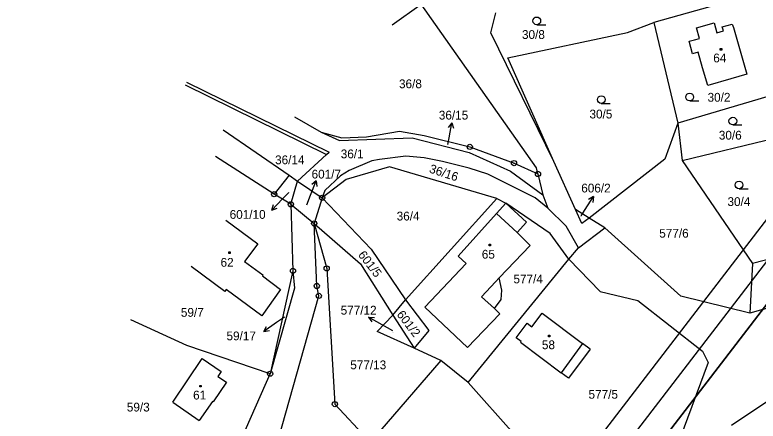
# Model space of a CAD drawing. Extents: x -866656 to -858817, y -1041816 to -1038653.
# Drawn here: x -862913.4 to -862769.6, y -1039656.9 to -1039578.3 of the extents above; entities that cross this region are included whole.
import ezdxf

# ---------------------------------------------------------------- set-up
doc = ezdxf.new("R2010")
doc.units = 0
for name, color, linetype in [('tisk ramy', 7, 'Continuous'), ('Vrstva 1', 7, 'Continuous'), ('Vrstva 2', 7, 'Continuous')]:
    doc.layers.add(name, color=color, linetype=linetype)

msp = doc.modelspace()

# ---------------------------------------------------------------- linework, layer by layer
at = {"layer": 'tisk ramy'}
for points in [[(-862750.99, -1040083.46), (-861983.98, -1039083.83), (-862219.6, -1038903.04), (-862986.61, -1039902.67)], [(-862979.6, -1039901.75), (-862218.68, -1038910.05), (-861990.99, -1039084.75), (-862751.92, -1040076.45)], [(-862752.84, -1040069.45), (-862122.79, -1039248.31), (-862342.55, -1039079.69), (-862972.6, -1039900.83)], [(-862972.6, -1039900.83), (-862342.55, -1039079.69), (-862122.79, -1039248.31), (-862752.84, -1040069.45)]]:
    msp.add_lwpolyline(points, close=True, dxfattribs=at)
at = {"layer": 'Vrstva 1'}
for p, q in [((-862770.51, -1039574.3), (-862789.82, -1039579.76)), ((-862840.39, -1039580.21), (-862834.77, -1039576.2)), ((-862812.5, -1039607.85), (-862834.77, -1039576.2)), ((-862821.31, -1039581.76), (-862820.36, -1039577.84)), ((-862812.44, -1039580.18), (-862810.69, -1039580.18)), ((-862794.91, -1039581.68), (-862789.82, -1039579.76)), ((-862789.82, -1039579.76), (-862785.16, -1039599.23)), ((-862781.58, -1039580.79), (-862778.16, -1039579.81)), ((-862780.99, -1039582.81), (-862781.58, -1039580.79)), ((-862778.16, -1039579.81), (-862777.61, -1039581.73)), ((-862776.57, -1039580.59), (-862774.65, -1039580.03)), ((-862776.35, -1039581.36), (-862776.57, -1039580.59)), ((-862774.65, -1039580.03), (-862774.43, -1039580.71)), ((-862774.43, -1039580.71), (-862771.84, -1039589.74)), ((-862809.11, -1039606.61), (-862821.31, -1039581.76)), ((-862818.05, -1039586.59), (-862794.91, -1039581.68)), ((-862777.61, -1039581.73), (-862776.35, -1039581.36)), ((-862782.99, -1039583.38), (-862781.94, -1039583.07)), ((-862782.3, -1039585.8), (-862782.99, -1039583.38)), ((-862781.94, -1039583.07), (-862780.99, -1039582.81)), ((-862776.97, -1039584.76), (-862776.67, -1039584.76)), ((-862776.97, -1039585.06), (-862776.97, -1039584.76)), ((-862776.67, -1039585.06), (-862776.97, -1039585.06)), ((-862776.67, -1039584.76), (-862776.67, -1039585.06)), ((-862781.25, -1039585.5), (-862782.3, -1039585.8)), ((-862780.38, -1039588.48), (-862781.25, -1039585.5)), ((-862809.11, -1039606.61), (-862818.05, -1039586.59)), ((-862779.39, -1039591.95), (-862780.38, -1039588.48)), ((-862774.91, -1039590.63), (-862779.39, -1039591.95)), ((-862771.84, -1039589.74), (-862774.91, -1039590.63)), ((-862880.42, -1039591.79), (-862853.1, -1039605.3)), ((-862880.14, -1039591.3), (-862852.58, -1039604.82)), ((-862765.99, -1039593.51), (-862785.16, -1039599.23)), ((-862782.87, -1039594.91), (-862781.12, -1039594.91)), ((-862799.97, -1039595.4), (-862798.22, -1039595.4)), ((-862859.31, -1039597.97), (-862854.15, -1039600.97)), ((-862828.88, -1039599.13), (-862829.54, -1039600.02)), ((-862829.4, -1039602.08), (-862828.88, -1039599.13)), ((-862828.88, -1039599.13), (-862828.56, -1039600.2)), ((-862785.16, -1039599.23), (-862787.66, -1039606.21)), ((-862785.16, -1039599.23), (-862784.34, -1039606.44)), ((-862873.05, -1039600.53), (-862860.32, -1039609.3)), ((-862845.36, -1039601.88), (-862838.98, -1039600.73)), ((-862838.98, -1039600.73), (-862834.19, -1039601.57)), ((-862784.34, -1039606.44), (-862761.09, -1039600.84)), ((-862774.53, -1039599.56), (-862772.78, -1039599.56)), ((-862854.15, -1039600.97), (-862850.56, -1039602.54)), ((-862854.15, -1039600.97), (-862850.16, -1039602.05)), ((-862850.56, -1039602.54), (-862836.56, -1039602.05)), ((-862850.16, -1039602.05), (-862845.36, -1039601.88)), ((-862836.56, -1039602.05), (-862825.52, -1039604.89)), ((-862834.19, -1039601.57), (-862825.39, -1039603.8)), ((-862829.63, -1039603.35), (-862829.4, -1039602.08)), ((-862825.39, -1039603.8), (-862816.84, -1039606.94)), ((-862853.1, -1039605.3), (-862852.58, -1039604.82)), ((-862825.52, -1039604.89), (-862817.53, -1039608.5)), ((-862863.21, -1039612.96), (-862874.56, -1039605.69)), ((-862853.1, -1039605.3), (-862858.68, -1039610.42)), ((-862844.36, -1039606.52), (-862848.69, -1039608.37)), ((-862842.85, -1039606.22), (-862844.36, -1039606.52)), ((-862837.78, -1039605.62), (-862842.85, -1039606.22)), ((-862834.21, -1039605.92), (-862837.78, -1039605.62)), ((-862830.65, -1039606.62), (-862834.21, -1039605.92)), ((-862825.48, -1039607.93), (-862830.65, -1039606.62)), ((-862804.98, -1039615.9), (-862809.11, -1039606.61)), ((-862787.66, -1039606.21), (-862802.29, -1039617.58)), ((-862784.34, -1039606.44), (-862770.71, -1039626.39)), ((-862840.92, -1039607.67), (-862849.28, -1039610.11)), ((-862820.17, -1039613.81), (-862840.92, -1039607.67)), ((-862821.88, -1039609.11), (-862825.48, -1039607.93)), ((-862816.84, -1039606.94), (-862812.21, -1039609.04)), ((-862812.21, -1039609.04), (-862812.5, -1039607.85)), ((-862860.32, -1039609.3), (-862863.21, -1039612.96)), ((-862860.32, -1039609.3), (-862858.68, -1039610.42)), ((-862850.37, -1039609.4), (-862853.4, -1039612.23)), ((-862848.69, -1039608.37), (-862850.37, -1039609.4)), ((-862812.78, -1039613.66), (-862821.88, -1039609.11)), ((-862817.53, -1039608.5), (-862811.24, -1039613.09)), ((-862812.21, -1039609.04), (-862811.24, -1039613.09)), ((-862859.99, -1039614.91), (-862858.68, -1039610.42)), ((-862858.68, -1039610.42), (-862853.94, -1039613.65)), ((-862856.17, -1039613.16), (-862855.08, -1039610.36)), ((-862855.08, -1039610.36), (-862855.91, -1039611.11)), ((-862855.08, -1039610.36), (-862854.98, -1039611.48)), ((-862849.28, -1039610.11), (-862853.94, -1039613.65)), ((-862853.4, -1039612.23), (-862853.94, -1039613.65)), ((-862773.33, -1039611.91), (-862771.58, -1039611.91)), ((-862861.61, -1039613.85), (-862863.68, -1039616.02)), ((-862859.99, -1039614.91), (-862863.21, -1039612.96)), ((-862860.41, -1039612.6), (-862861.61, -1039613.85)), ((-862856.89, -1039615), (-862856.17, -1039613.16)), ((-862853.94, -1039613.65), (-862855.47, -1039618.62)), ((-862853.94, -1039613.65), (-862844.43, -1039623.58)), ((-862837.79, -1039633.37), (-862820.17, -1039613.81)), ((-862820.17, -1039613.81), (-862818.44, -1039614.72)), ((-862810.29, -1039615.68), (-862812.78, -1039613.66)), ((-862811.24, -1039613.09), (-862810.29, -1039615.68)), ((-862803.08, -1039615.94), (-862801.45, -1039613.42)), ((-862801.45, -1039613.42), (-862802.41, -1039613.99)), ((-862801.45, -1039613.42), (-862801.57, -1039614.53)), ((-862863.68, -1039616.02), (-862863.35, -1039614.95)), ((-862859.99, -1039614.91), (-862859.58, -1039627.78)), ((-862859.99, -1039614.91), (-862855.47, -1039618.62)), ((-862818.44, -1039614.72), (-862820.25, -1039616.67)), ((-862814.43, -1039618.37), (-862818.44, -1039614.72)), ((-862809.88, -1039620.57), (-862818.44, -1039614.72)), ((-862863.68, -1039616.02), (-862862.63, -1039615.64)), ((-862820.25, -1039616.67), (-862827.61, -1039624.94)), ((-862806.76, -1039619.17), (-862810.29, -1039615.68)), ((-862803.72, -1039618.65), (-862804.98, -1039615.9)), ((-862802.29, -1039617.58), (-862804.98, -1039615.9)), ((-862803.87, -1039617.15), (-862803.08, -1039615.94)), ((-862872.58, -1039617.97), (-862866.4, -1039622.58)), ((-862802.29, -1039617.58), (-862803.72, -1039618.65)), ((-862799.28, -1039619.47), (-862802.29, -1039617.58)), ((-862855.47, -1039618.62), (-862846.52, -1039626.45)), ((-862855.47, -1039618.62), (-862853.06, -1039627.31)), ((-862854.97, -1039630.71), (-862855.47, -1039618.62)), ((-862816.26, -1039620.39), (-862814.43, -1039618.37)), ((-862804.37, -1039623.3), (-862806.76, -1039619.17)), ((-862804.37, -1039623.3), (-862799.28, -1039619.47)), ((-862799.28, -1039619.47), (-862784.58, -1039632.7)), ((-862813.74, -1039622.88), (-862816.26, -1039620.39)), ((-862806.27, -1039625.51), (-862809.88, -1039620.57)), ((-862866.4, -1039622.58), (-862868.94, -1039625.97)), ((-862844.43, -1039623.58), (-862837.79, -1039633.37)), ((-862821.67, -1039622.64), (-862821.37, -1039622.64)), ((-862821.67, -1039622.94), (-862821.67, -1039622.64)), ((-862821.37, -1039622.94), (-862821.67, -1039622.94)), ((-862821.37, -1039622.64), (-862821.37, -1039622.94)), ((-862813.74, -1039622.88), (-862819.72, -1039629.16)), ((-862806.27, -1039625.51), (-862804.37, -1039623.3)), ((-862759.46, -1039623.4), (-862770.71, -1039626.39)), ((-862872, -1039624.11), (-862871.7, -1039624.11)), ((-862872, -1039624.41), (-862872, -1039624.11)), ((-862871.7, -1039624.41), (-862872, -1039624.41)), ((-862871.7, -1039624.11), (-862871.7, -1039624.41)), ((-862827.61, -1039624.94), (-862826.1, -1039626.37)), ((-862868.94, -1039625.97), (-862865.4, -1039628.58)), ((-862846.52, -1039626.45), (-862840.27, -1039636.34)), ((-862826.1, -1039626.37), (-862834.08, -1039634.82)), ((-862825.72, -1039649.41), (-862806.27, -1039625.51)), ((-862800.19, -1039631.78), (-862806.27, -1039625.51)), ((-862770.71, -1039626.39), (-862771.22, -1039636)), ((-862872.73, -1039631.79), (-862879.28, -1039626.96)), ((-862859.58, -1039627.78), (-862863.99, -1039647.69)), ((-862859.58, -1039627.78), (-862859.26, -1039631.15)), ((-862853.06, -1039627.31), (-862851.48, -1039653.57)), ((-862865.4, -1039628.58), (-862865.5, -1039628.72)), ((-862865.5, -1039628.72), (-862861.96, -1039631.41)), ((-862819.19, -1039631.55), (-862819.72, -1039629.16)), ((-862854.58, -1039632.63), (-862854.97, -1039630.71)), ((-862754.3, -1039631.12), (-862771.22, -1039636)), ((-862872.48, -1039631.42), (-862872.73, -1039631.79)), ((-862865.57, -1039636.48), (-862872.48, -1039631.42)), ((-862861.96, -1039631.41), (-862865.57, -1039636.48)), ((-862859.26, -1039631.15), (-862863.99, -1039647.69)), ((-862819.33, -1039633.3), (-862819.19, -1039631.55)), ((-862800.19, -1039631.78), (-862792.93, -1039633.52)), ((-862866.73, -1039675.64), (-862854.58, -1039632.63)), ((-862840.27, -1039636.34), (-862837.79, -1039633.37)), ((-862837.79, -1039633.37), (-862833.34, -1039639.35)), ((-862820.6, -1039635.08), (-862819.33, -1039633.3)), ((-862792.93, -1039633.52), (-862780.41, -1039643.29)), ((-862771.22, -1039636), (-862784.58, -1039632.7)), ((-862834.08, -1039634.82), (-862825.82, -1039642.61)), ((-862819.56, -1039636.11), (-862820.6, -1039635.08)), ((-862861.23, -1039636.75), (-862862.74, -1039637.8)), ((-862842.33, -1039638.21), (-862844.95, -1039636.75)), ((-862844.95, -1039636.75), (-862844.32, -1039637.67)), ((-862844.95, -1039636.75), (-862843.83, -1039636.8)), ((-862843.28, -1039639.49), (-862840.27, -1039636.34)), ((-862840.27, -1039636.34), (-862836.17, -1039642.75)), ((-862825.82, -1039642.61), (-862819.56, -1039636.11)), ((-862813.37, -1039638.6), (-862811.41, -1039635.99)), ((-862811.41, -1039635.99), (-862803.57, -1039641.87)), ((-862880.1, -1039642.23), (-862890.92, -1039637.28)), ((-862862.74, -1039637.8), (-862865.2, -1039639.52)), ((-862840.27, -1039639.36), (-862842.33, -1039638.21)), ((-862816.42, -1039640.76), (-862814.29, -1039637.91)), ((-862814.29, -1039637.91), (-862813.37, -1039638.6)), ((-862865.2, -1039639.52), (-862864.67, -1039638.53)), ((-862865.2, -1039639.52), (-862864.09, -1039639.35)), ((-862836.17, -1039642.75), (-862843.28, -1039639.49)), ((-862833.34, -1039639.35), (-862836.17, -1039642.75)), ((-862815.47, -1039641.47), (-862816.42, -1039640.76)), ((-862810.19, -1039640.23), (-862809.89, -1039640.23)), ((-862810.19, -1039640.53), (-862810.19, -1039640.23)), ((-862809.89, -1039640.53), (-862810.19, -1039640.53)), ((-862809.89, -1039640.23), (-862809.89, -1039640.53)), ((-862863.99, -1039647.69), (-862880.1, -1039642.23)), ((-862815.47, -1039641.47), (-862815.58, -1039641.61)), ((-862815.58, -1039641.61), (-862807.74, -1039647.49)), ((-862802.12, -1039642.94), (-862803.57, -1039641.87)), ((-862830.97, -1039645.13), (-862836.17, -1039642.75)), ((-862802.12, -1039642.94), (-862806.29, -1039648.56)), ((-862780.41, -1039643.29), (-862779.32, -1039645.5)), ((-862882.8, -1039653.16), (-862877.11, -1039644.77)), ((-862877.11, -1039644.77), (-862873.46, -1039647.26)), ((-862830.97, -1039645.13), (-862842.8, -1039658.78)), ((-862825.72, -1039649.41), (-862830.97, -1039645.13)), ((-862779.32, -1039645.5), (-862786.68, -1039665.41)), ((-862873.46, -1039647.26), (-862874.12, -1039648.23)), ((-862874.12, -1039648.23), (-862872.46, -1039649.34)), ((-862872.47, -1039666.84), (-862863.99, -1039647.69)), ((-862806.29, -1039648.56), (-862807.74, -1039647.49)), ((-862872.46, -1039649.34), (-862875.01, -1039653.13)), ((-862816.85, -1039659.32), (-862825.72, -1039649.41)), ((-862877.6, -1039649.95), (-862877.3, -1039649.95)), ((-862877.6, -1039650.25), (-862877.6, -1039649.95)), ((-862877.3, -1039650.25), (-862877.6, -1039650.25)), ((-862877.3, -1039649.95), (-862877.3, -1039650.25)), ((-862774.79, -1039657.64), (-862766.81, -1039652.29)), ((-862882.8, -1039653.16), (-862877.69, -1039656.76)), ((-862875.12, -1039653.06), (-862877.69, -1039656.76)), ((-862875.01, -1039653.13), (-862875.12, -1039653.06)), ((-862844.26, -1039661.29), (-862851.48, -1039653.57))]:
    msp.add_line(p, q, dxfattribs=at)
for centre, radius in [((-862812.44, -1039579.43), 0.75), ((-862782.87, -1039594.16), 0.75), ((-862799.97, -1039594.65), 0.75), ((-862774.53, -1039598.81), 0.75), ((-862825.39, -1039603.8), 0.5), ((-862825.39, -1039603.8), 0.01), ((-862816.84, -1039606.94), 0.5), ((-862816.84, -1039606.94), 0.01), ((-862812.21, -1039609.04), 0.5), ((-862812.21, -1039609.04), 0.01), ((-862773.33, -1039611.16), 0.75), ((-862863.21, -1039612.96), 0.5), ((-862863.21, -1039612.96), 0.01), ((-862853.94, -1039613.65), 0.5), ((-862853.94, -1039613.65), 0.01), ((-862859.99, -1039614.91), 0.5), ((-862859.99, -1039614.91), 0.01), ((-862855.47, -1039618.62), 0.5), ((-862855.47, -1039618.62), 0.01), ((-862853.06, -1039627.31), 0.5), ((-862859.58, -1039627.78), 0.5), ((-862859.58, -1039627.78), 0.01), ((-862853.06, -1039627.31), 0.01), ((-862854.97, -1039630.71), 0.5), ((-862854.97, -1039630.71), 0.01), ((-862854.58, -1039632.63), 0.5), ((-862854.58, -1039632.63), 0.01), ((-862863.99, -1039647.69), 0.5), ((-862863.99, -1039647.69), 0.01), ((-862851.48, -1039653.57), 0.5), ((-862851.48, -1039653.57), 0.01)]:
    msp.add_circle(centre, radius, dxfattribs=at)
at = {"layer": 'Vrstva 2'}
for p, q in [((-862820.25, -1039616.67), (-862816.26, -1039620.39)), ((-862819.72, -1039629.16), (-862820.42, -1039629.91)), ((-862820.42, -1039629.91), (-862823.12, -1039632.8)), ((-862823.12, -1039632.8), (-862820.6, -1039635.08)), ((-862803.57, -1039641.87), (-862807.74, -1039647.49))]:
    msp.add_line(p, q, dxfattribs=at)

# ---------------------------------------------------------------- texts
at = {"layer": 'Vrstva 1'}
for s, height, p in [('30/8', 1.7, (-862815.3, -1039582.92)), ('64', 1.7, (-862778.32, -1039587.45)), ('36/8', 1.7, (-862839.08, -1039592.45)), ('30/2', 1.7, (-862779.42, -1039595.06)), ('30/5', 1.7, (-862802.25, -1039598.3)), ('36/15', 1.7, (-862831.38, -1039598.51)), ('30/6', 1.7, (-862777.24, -1039602.39)), ('36/15', 0.1, (-862829.8, -1039603.35)), ('36/1', 1.7, (-862850.34, -1039606.01)), ('36/14', 1.7, (-862863.04, -1039607.16)), ('601/7', 1.7, (-862855.98, -1039609.92)), ('606/2', 1.7, (-862803.84, -1039612.62)), ('601/10', 0.1, (-862860.61, -1039612.6)), ('30/4', 1.7, (-862775.57, -1039615.24)), ('601/7', 0.1, (-862857.06, -1039615)), ('601/10', 1.7, (-862871.82, -1039617.72)), ('36/4', 1.7, (-862839.53, -1039618.04)), ('606/2', 0.1, (-862804.01, -1039617.34)), ('577/6', 1.7, (-862788.76, -1039621.36)), ('65', 1.7, (-862823.07, -1039625.42)), ('62', 1.7, (-862873.58, -1039626.99)), ('577/4', 1.7, (-862816.95, -1039630.2)), ('59/7', 1.7, (-862881.25, -1039636.67)), ('577/12', 1.7, (-862850.36, -1039636.25)), ('59/17', 0.1, (-862861.4, -1039636.75)), ('59/17', 1.7, (-862872.43, -1039641.22)), ('577/12', 0.1, (-862840.47, -1039639.76)), ('58', 1.7, (-862811.45, -1039642.94)), ('577/13', 1.7, (-862848.5, -1039646.82)), ('61', 1.7, (-862878.89, -1039652.67)), ('577/5', 1.7, (-862802.43, -1039652.52)), ('59/3', 1.7, (-862891.7, -1039654.99))]:
    msp.add_text(s, height=height, dxfattribs=at).set_placement(p)
for s, rotation, p in [('36/16', 341.7949, (-862833.36, -1039608.72)), ('601/5', 307.5239, (-862847.08, -1039624.71)), ('601/2', 307.5239, (-862839.61, -1039636.25))]:
    msp.add_text(s, height=1.7, rotation=rotation, dxfattribs=at).set_placement(p)

doc.saveas('drawing.dxf')
